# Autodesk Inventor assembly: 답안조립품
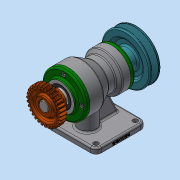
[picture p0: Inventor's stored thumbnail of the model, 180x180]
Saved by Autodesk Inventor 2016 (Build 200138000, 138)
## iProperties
Created: 2019-01
Part Number: 답안조립품
Material: 일반
Document SubType Name: Assembly
Designer: Administrator
Author: Administrator
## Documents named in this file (15)
- C:\Users\Administrator\Desktop\490107V1016\답안조립품.iam
- C:\Users\Administrator\Desktop\490107V1016\본체.ipt
- C:\Users\Administrator\Desktop\490107V1016\베어링 6205.ipt
- C:\Users\Administrator\Desktop\490107V1016\앞커버.ipt
- C:\Users\Administrator\Desktop\490107V1016\볼트 M4.ipt
- C:\Users\Administrator\Desktop\490107V1016\축.ipt
- C:\Users\Administrator\Desktop\490107V1016\베어링 6203.ipt
- C:\Users\Administrator\Desktop\490107V1016\뒤커버.ipt
- C:\Users\Administrator\Desktop\490107V1016\오일 실 25 38 8.ipt
- C:\Users\Administrator\Desktop\490107V1016\오일 실 17 30 8.ipt
- C:\Users\Administrator\Desktop\490107V1016\키 6 x 6 x 18.ipt
- C:\Users\Administrator\Desktop\490107V1016\키 5 x 5 x 20.ipt
- C:\Users\Administrator\Desktop\490107V1016\스퍼기어.ipt
- C:\Users\Administrator\Desktop\490107V1016\V-벨트풀리.ipt
- C:\Users\Administrator\Desktop\490107V1016\멈춤나사 M3.ipt
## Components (1 placed, 1 different names)
1. V-벨트풀리:3
